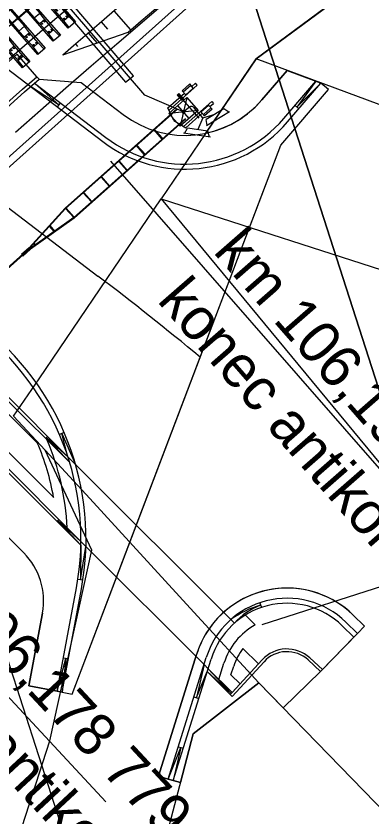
# Model space of a CAD drawing. Extents: x -758836 to -757729, y -1175316 to -1174366.
# Drawn here: x -758398.33 to -758387.81, y -1174860.97 to -1174837.29 of the extents above; entities that cross this region are included whole.
import ezdxf

# ---------------------------------------------------------------- set-up
doc = ezdxf.new("R2010")
doc.units = 0
for name, color, linetype in [('_NOR-návrh silná', 7, 'Continuous'), ('_NOR-návrh tenká', 7, 'Continuous'), ('_NOR-osa', 7, 'Continuous'), ('_NOR-pomocná', 7, 'Continuous'), ('_NOR-popis', 7, 'Continuous'), ('_NOR-pražce', 7, 'Continuous'), ('_NOR-přejezdová konstrukce', 7, 'Continuous'), ('_NOR-sanace', 7, 'Continuous'), ('_NOR-svahy', 7, 'Continuous'), ('G_Obvod stavby', 7, 'Continuous'), ('Hranice parcel', 7, 'Continuous'), ('KOS_kabely SSZT', 7, 'Continuous'), ('KOS_PZZ nové', 7, 'Continuous'), ('Vrstva 1', 7, 'Continuous')]:
    doc.layers.add(name, color=color, linetype=linetype)

# ---------------------------------------------------------------- blocks, each defined once
blk = doc.blocks.new('půdorys-SB8')
at = {"layer": '_NOR-pražce'}
for p, q in [((-1.21, 0.109), (-0.96, 0.095)), ((-0.96, 0.095), (-0.56, 0.099)), ((-0.96, 0.095), (-0.96, -0.095)), ((-0.56, 0.099), (-0.32, 0.109)), ((-0.56, 0.099), (-0.56, -0.1)), ((-0.32, 0.109), (0.32, 0.109)), ((-0.32, 0.109), (-0.32, -0.11)), ((0.56, 0.099), (0.32, 0.109)), ((0.32, -0.11), (0.32, 0.109)), ((0.96, 0.095), (0.56, 0.099)), ((0.56, 0.099), (0.56, -0.1)), ((1.21, 0.109), (0.96, 0.095)), ((0.96, 0.095), (0.96, -0.095)), ((-1.21, -0.11), (-0.96, -0.095)), ((-0.96, -0.095), (-0.56, -0.1)), ((-0.56, -0.1), (-0.32, -0.11)), ((-0.32, -0.11), (0.32, -0.11)), ((0.56, -0.1), (0.32, -0.11)), ((0.96, -0.095), (0.56, -0.1)), ((1.21, -0.11), (0.96, -0.095))]:
    blk.add_line(p, q, dxfattribs=at)
blk.add_lwpolyline([(-1.21, 0.142), (1.21, 0.142), (1.21, -0.142), (-1.21, -0.142)], close=True, dxfattribs=at)
for centre in [(-0.916, 0.048), (-0.604, 0.048), (0.604, 0.048), (0.916, 0.048), (-0.916, -0.048), (-0.604, -0.048), (0.604, -0.048), (0.916, -0.048)]:
    blk.add_circle(centre, 0.015, dxfattribs=at)
blk = doc.blocks.new('Závora 8m')
for p, q in [((0.083, -0.373), (-0.058, -0.373)), ((-0.058, -0.448), (-0.058, -0.373)), ((1.054, -0.448), (-0.058, -0.448)), ((1.032, -0.373), (0.382, -0.373)), ((0.542, -0.323), (0.542, -1.27)), ((1.149, -0.771), (1.032, -0.373)), ((0.413, -1.026), (1.122, -0.517)), ((0.413, -0.517), (1.122, -1.026)), ((0.767, -0.517), (0.767, -1.026)), ((0.851, -0.571), (5.271, -0.571)), ((0.851, -0.591), (5.271, -0.591)), ((1.751, -0.591), (1.751, -0.951)), ((1.771, -0.591), (1.771, -0.951)), ((2.451, -0.591), (2.451, -0.951)), ((2.471, -0.591), (2.471, -0.951)), ((3.151, -0.591), (3.151, -0.951)), ((3.171, -0.591), (3.171, -0.951)), ((3.851, -0.591), (3.851, -0.951)), ((3.871, -0.591), (3.871, -0.951)), ((4.551, -0.591), (4.551, -0.951)), ((4.571, -0.591), (4.571, -0.951)), ((5.251, -0.591), (5.251, -0.951)), ((5.271, -0.571), (6.851, -0.741)), ((5.271, -0.591), (5.271, -0.951)), ((5.271, -0.591), (6.851, -0.761)), ((5.951, -0.665), (5.951, -0.878)), ((5.971, -0.667), (5.971, -0.876)), ((1.149, -0.771), (1.032, -1.17)), ((6.851, -0.781), (5.271, -0.951)), ((5.271, -0.971), (6.851, -0.801)), ((6.651, -0.74), (6.651, -0.803)), ((6.671, -0.742), (6.671, -0.801)), ((6.851, -0.741), (7.151, -0.741)), ((8.851, -0.761), (6.851, -0.761)), ((6.851, -0.761), (6.851, -0.781)), ((6.851, -0.761), (7.151, -0.761)), ((8.851, -0.781), (6.851, -0.781)), ((6.851, -0.781), (7.151, -0.781)), ((6.851, -0.801), (7.151, -0.801)), ((7.151, -0.741), (7.151, -0.761)), ((7.151, -0.801), (7.151, -0.781)), ((8.851, -0.761), (8.851, -0.781)), ((1.054, -1.095), (-0.058, -1.095)), ((-0.058, -1.095), (-0.058, -1.17)), ((0.083, -1.17), (-0.058, -1.17)), ((1.032, -1.17), (0.382, -1.17)), ((0.851, -0.951), (5.271, -0.951)), ((0.851, -0.971), (5.271, -0.971))]:
    blk.add_line(p, q)
for points in [[(0.382, -0.434), (0.083, -0.434), (0.083, -0.274), (0.382, -0.274)], [(0.382, -0.324), (0.083, -0.324), (0.083, -0.274), (0.382, -0.274)], [(0.413, -0.517), (1.122, -0.517), (1.122, -1.026), (0.413, -1.026)], [(0.382, -1.109), (0.083, -1.109), (0.083, -1.269), (0.382, -1.269)], [(0.382, -1.219), (0.083, -1.219), (0.083, -1.269), (0.382, -1.269)]]:
    blk.add_lwpolyline(points, close=True)
blk.add_lwpolyline([(0.507, -1.048), (0.507, -1.27), (0.578, -1.27), (0.578, -1.048)])
for start, end in [(130.1075, 310.1075), (310.1075, 130.1075)]:
    blk.add_arc((0.767, -0.771), 0.0422, start, end)
blk = doc.blocks.new('A$C45C32C5D')
for p, q in [((0.338, 0.725), (0, 0)), ((0.328, 0.702), (0.449, 0.568)), ((0.011, 0.023), (0.192, 0.016))]:
    blk.add_line(p, q)
blk.add_lwpolyline([(0.449, 0.568), (0.192, 0.016)])
blk = doc.blocks.new('A$C45E25FDC')
for p, q in [((0.029, 0.671), (0.224, 0.671)), ((0.341, 0.159), (0.341, 0.557)), ((0.341, 0.159), (0, 0))]:
    blk.add_line(p, q)
blk.add_arc((0.227, 0.557), 0.115, 0.0129, 91.4438)

msp = doc.modelspace()

# ---------------------------------------------------------------- linework, layer by layer
at = {"layer": '_NOR-návrh silná'}
for p, q in [((-758398.635, -1174848.483), (-758396.798, -1174850.321)), ((-758399.199, -1174850.041), (-758396.41, -1174852.83)), ((-758388.58, -1174855.21), (-758388.234, -1174855.546)), ((-758393.827, -1174859.853), (-758392.706, -1174856.261)), ((-758389.269, -1174856.616), (-758389.641, -1174856.272)), ((-758391.944, -1174857.296), (-758391.056, -1174856.33)), ((-758392.651, -1174856.589), (-758391.944, -1174857.296))]:
    msp.add_line(p, q, dxfattribs=at)
for points in [[(-758409.317, -1174830.673), (-758395.764, -1174841.002)], [(-758390.302, -1174840.423), (-758389.316, -1174839.272)], [(-758396.968, -1174857.284), (-758396.396, -1174854.23)]]:
    msp.add_lwpolyline(points, dxfattribs=at)
for centre, radius, start, end in [((-758393.34, -1174837.82), 4, 232.6885, 319.4185), ((-758404.26, -1174852.758), 8, 349.3996, 52.6885), ((-758390.32, -1174857.006), 2.5, 45.9171, 162.6626), ((-758390.32, -1174857.006), 1, 47.2605, 137.4155)]:
    msp.add_arc(centre, radius, start, end, dxfattribs=at)
at = {"layer": '_NOR-návrh tenká'}
for p, q in [((-758410.366, -1174852.055), (-758391.422, -1174835.079)), ((-758410.212, -1174852.218), (-758391.278, -1174835.252)), ((-758389.466, -1174839.216), (-758390.023, -1174839.982)), ((-758397.056, -1174839.923), (-758397.897, -1174839.377)), ((-758397.781, -1174839.276), (-758397.056, -1174839.923)), ((-758390.023, -1174839.982), (-758389.316, -1174839.272)), ((-758397.101, -1174839.983), (-758397.01, -1174839.863)), ((-758389.966, -1174840.031), (-758390.08, -1174839.934)), ((-758398.665, -1174848.567), (-758396.746, -1174850.486)), ((-758398.767, -1174848.847), (-758397.7, -1174849.914)), ((-758396.907, -1174849.607), (-758397.045, -1174849.666)), ((-758396.798, -1174850.321), (-758396.976, -1174849.636)), ((-758396.976, -1174849.636), (-758396.571, -1174850.548)), ((-758399.067, -1174849.678), (-758397.216, -1174851.529)), ((-758397.453, -1174849.779), (-758397.396, -1174849.723)), ((-758396.746, -1174850.486), (-758397.425, -1174849.751)), ((-758397.425, -1174849.751), (-758396.798, -1174850.321)), ((-758399.229, -1174850.124), (-758396.412, -1174852.941)), ((-758396.798, -1174850.321), (-758396.571, -1174850.548)), ((-758396.571, -1174850.548), (-758391.981, -1174855.138)), ((-758397.119, -1174852.234), (-758397.063, -1174852.178)), ((-758396.412, -1174852.941), (-758397.091, -1174852.206)), ((-758397.091, -1174852.206), (-758396.41, -1174852.83)), ((-758396.412, -1174852.941), (-758396.427, -1174853.961)), ((-758396.427, -1174853.961), (-758396.263, -1174852.977)), ((-758396.41, -1174852.83), (-758396.263, -1174852.977)), ((-758392.771, -1174856.469), (-758396.263, -1174852.977)), ((-758396.353, -1174853.972), (-758396.501, -1174853.949)), ((-758391.122, -1174854.639), (-758391.074, -1174854.781)), ((-758391.549, -1174855.004), (-758391.257, -1174855.296)), ((-758391.981, -1174855.138), (-758391.875, -1174855.244)), ((-758388.685, -1174855.318), (-758388.338, -1174855.654)), ((-758389.325, -1174856.673), (-758388.234, -1174855.546)), ((-758391.621, -1174855.992), (-758391.165, -1174856.449)), ((-758397.115, -1174857.256), (-758396.858, -1174856.287)), ((-758396.858, -1174856.287), (-758396.968, -1174857.284)), ((-758396.784, -1174856.301), (-758396.931, -1174856.274)), ((-758393.684, -1174859.898), (-758392.563, -1174856.306)), ((-758392.771, -1174856.469), (-758392.997, -1174857.446)), ((-758392.771, -1174856.469), (-758392.651, -1174856.589)), ((-758392.332, -1174856.908), (-758392.181, -1174856.425)), ((-758391.975, -1174856.771), (-758391.895, -1174856.515)), ((-758391.942, -1174857.412), (-758390.997, -1174856.384)), ((-758389.325, -1174856.673), (-758389.695, -1174856.331)), ((-758392.997, -1174857.446), (-758392.678, -1174856.675)), ((-758392.678, -1174856.675), (-758391.942, -1174857.412)), ((-758392.678, -1174856.675), (-758391.972, -1174857.324)), ((-758391.972, -1174857.324), (-758392.651, -1174856.589)), ((-758391.975, -1174856.771), (-758391.707, -1174857.038)), ((-758393.069, -1174857.424), (-758392.926, -1174857.468)), ((-758391.944, -1174857.296), (-758392.001, -1174857.353)), ((-758393.529, -1174858.899), (-758393.386, -1174858.943)), ((-758393.827, -1174859.853), (-758393.458, -1174858.921)), ((-758393.458, -1174858.921), (-758393.684, -1174859.898)), ((-758393.827, -1174859.853), (-758393.684, -1174859.898))]:
    msp.add_line(p, q, dxfattribs=at)
for points in [[(-758396.95, -1174838.443), (-758396.628, -1174838.163), (-758395.875, -1174837.512), (-758395.12, -1174836.864), (-758394.364, -1174836.218), (-758393.605, -1174835.574), (-758392.844, -1174834.933), (-758392.082, -1174834.295), (-758391.318, -1174833.659), (-758390.551, -1174833.025), (-758389.782, -1174832.394)], [(-758396.95, -1174838.443), (-758395.018, -1174837.764), (-758394.632, -1174837.434), (-758393.877, -1174836.789), (-758393.121, -1174836.147), (-758392.362, -1174835.508), (-758391.601, -1174834.871), (-758390.839, -1174834.236), (-758390.074, -1174833.604), (-758389.306, -1174832.974)], [(-758398.755, -1174838.756), (-758398.003, -1174838.099), (-758397.25, -1174837.445), (-758396.495, -1174836.792)], [(-758391.061, -1174839.772), (-758390.315, -1174838.9), (-758389.466, -1174839.216)], [(-758397.65, -1174839.161), (-758396.408, -1174839.254), (-758395.158, -1174840.206)], [(-758390.416, -1174840.325), (-758389.466, -1174839.216), (-758389.316, -1174839.272)], [(-758397.781, -1174839.276), (-758395.673, -1174840.883)], [(-758396.968, -1174857.284), (-758396.673, -1174857.339), (-758390.499, -1174841.114), (-758389.088, -1174839.467), (-758389.316, -1174839.272)], [(-758401.824, -1174840.47), (-758395.906, -1174844.98)], [(-758398.099, -1174853.163), (-758399.469, -1174851.794)], [(-758396.968, -1174857.284), (-758397.115, -1174857.256), (-758396.544, -1174854.202)], [(-758397.115, -1174857.256), (-758397.951, -1174857.1), (-758397.548, -1174854.945)], [(-758388.234, -1174855.546), (-758388.025, -1174855.331), (-758388.372, -1174854.995)], [(-758392.992, -1174856.172), (-758394.114, -1174859.764), (-758393.827, -1174859.853)], [(-758393.684, -1174859.898), (-758393.467, -1174859.955), (-758393.09, -1174858.52), (-758391.15, -1174857.01), (-758390.43, -1174857.749), (-758389.325, -1174856.673)]]:
    msp.add_lwpolyline(points, dxfattribs=at)
for centre, radius, start, end in [((-758393.34, -1174837.82), 3, 232.6885, 319.4185), ((-758393.34, -1174837.82), 3.85, 232.6885, 319.4185), ((-758456.521, -1174924.515), 100, 50.47712, 52.68848), ((-758404.26, -1174852.758), 7.85, 349.3996, 52.6885), ((-758404.26, -1174852.758), 7.45, 2.5794, 23.2511), ((-758404.26, -1174852.758), 7.15, 9.8988, 23.4389), ((-758399.514, -1174854.577), 2, 349.3996, 45), ((-758390.32, -1174857.006), 2.8, 45.9171, 162.6626), ((-758390.32, -1174857.006), 2.35, 45.9171, 162.6626), ((-758390.317, -1174857.442), 2.842, 105.9509, 125.8252), ((-758390.38, -1174856.584), 2.007, 110.9778, 138.1294), ((-758390.32, -1174857.006), 1.95, 118.725, 162.6626), ((-758390.32, -1174857.006), 1.65, 142.0851, 162.6626), ((-758390.32, -1174857.006), 0.92, 47.2605, 137.4155)]:
    msp.add_arc(centre, radius, start, end, dxfattribs=at)
at = {"layer": '_NOR-osa'}
msp.add_lwpolyline([(-758398.496, -1174837.534), (-758397.741, -1174836.878)], dxfattribs=at)
at = {"layer": '_NOR-pomocná'}
for points in [[(-758417.595, -1174755.224), (-758317.652, -1174723.031), (-758272.123, -1174864.38), (-758372.066, -1174896.572)], [(-758517.538, -1174787.416), (-758417.595, -1174755.224), (-758372.066, -1174896.572), (-758472.009, -1174928.764)]]:
    msp.add_lwpolyline(points, close=True, dxfattribs=at)
at = {"layer": '_NOR-popis'}
for p, q in [((-758395.533, -1174841.585), (-758386.352, -1174852.094)), ((-758362.304, -1174846.032), (-758391.059, -1174855.295)), ((-758403.828, -1174851.775), (-758395.679, -1174860.526))]:
    msp.add_line(p, q, dxfattribs=at)
msp.add_lwpolyline([(-758398.823, -1174886.544), (-758389.781, -1174883.631), (-758402.76, -1174843.338)], dxfattribs=at)
at = {"layer": '_NOR-přejezdová konstrukce'}
msp.add_line((-758397.716, -1174839.086), (-758398.296, -1174838.422), dxfattribs=at)
for points in [[(-758404.537, -1174843.996), (-758403.933, -1174843.446), (-758403.193, -1174842.775), (-758402.452, -1174842.107), (-758401.709, -1174841.44), (-758400.965, -1174840.776), (-758400.219, -1174840.113), (-758399.471, -1174839.452), (-758398.722, -1174838.793), (-758398.296, -1174838.422)], [(-758403.943, -1174844.648), (-758403.34, -1174844.099), (-758402.602, -1174843.43), (-758401.862, -1174842.763), (-758401.121, -1174842.097), (-758400.378, -1174841.434), (-758399.634, -1174840.773), (-758398.888, -1174840.114), (-758398.14, -1174839.457), (-758397.716, -1174839.086)], [(-758403.943, -1174844.648), (-758403.876, -1174844.722), (-758403.272, -1174844.173), (-758402.534, -1174843.504), (-758401.795, -1174842.837), (-758401.054, -1174842.172), (-758400.312, -1174841.509), (-758399.568, -1174840.848), (-758398.822, -1174840.189), (-758398.074, -1174839.532), (-758397.65, -1174839.161), (-758397.716, -1174839.086)]]:
    msp.add_lwpolyline(points, dxfattribs=at)
at = {"layer": '_NOR-sanace'}
msp.add_lwpolyline([(-758398.347, -1174840.728), (-758397.601, -1174840.072), (-758396.854, -1174839.418), (-758396.104, -1174838.767), (-758395.353, -1174838.118), (-758394.6, -1174837.472), (-758393.845, -1174836.827)], dxfattribs=at)
at = {"layer": '_NOR-svahy'}
for points in [[(-758395.436, -1174837.135), (-758394.948, -1174837.704)], [(-758395.816, -1174837.461), (-758395.623, -1174837.685)], [(-758396.194, -1174837.788), (-758395.936, -1174838.087)], [(-758396.573, -1174838.115), (-758396.508, -1174838.19)], [(-758396.95, -1174838.443), (-758396.95, -1174838.443)]]:
    msp.add_lwpolyline(points, dxfattribs=at)
at = {"layer": 'G_Obvod stavby'}
for p, q in [((-758390.315, -1174838.9), (-758391.061, -1174839.772)), ((-758397.548, -1174854.945), (-758397.951, -1174857.1)), ((-758388.234, -1174855.546), (-758388.338, -1174855.654)), ((-758388.338, -1174855.654), (-758389.269, -1174856.616)), ((-758394.114, -1174859.764), (-758392.992, -1174856.172)), ((-758389.325, -1174856.673), (-758390.43, -1174857.749)), ((-758389.269, -1174856.616), (-758389.325, -1174856.673)), ((-758397.951, -1174857.1), (-758397.115, -1174857.256)), ((-758391.15, -1174857.01), (-758393.09, -1174858.52)), ((-758390.43, -1174857.749), (-758391.15, -1174857.01)), ((-758393.09, -1174858.52), (-758393.467, -1174859.955)), ((-758393.827, -1174859.853), (-758394.114, -1174859.764)), ((-758393.684, -1174859.898), (-758393.827, -1174859.853)), ((-758393.467, -1174859.955), (-758393.684, -1174859.898))]:
    msp.add_line(p, q, dxfattribs=at)
for points in [[(-758392.72, -1174840.756), (-758391.23, -1174838.56), (-758368.37, -1174821.64), (-758340.31, -1174807.33), (-758320.27, -1174796.89), (-758301, -1174790.21), (-758267.96, -1174782.93), (-758224.96, -1174775.27), (-758184.87, -1174772.83), (-758142.71, -1174770.26), (-758089.84, -1174768.68), (-758106.02, -1174731.44), (-758149.09, -1174725.67), (-758199.62, -1174726.6), (-758225.76, -1174732.36), (-758252.17, -1174738.18), (-758254.97, -1174739.34), (-758266.58, -1174744.16), (-758279.45, -1174749.49), (-758302.42, -1174759.02), (-758331.68, -1174770.24), (-758367.17, -1174799.81), (-758405.64, -1174832.2)], [(-758397.115, -1174857.256), (-758396.673, -1174857.339), (-758394.966, -1174852.852), (-758392.882, -1174847.378), (-758392.028, -1174845.133), (-758391.423, -1174843.542), (-758390.499, -1174841.114), (-758389.088, -1174839.467), (-758389.316, -1174839.272), (-758390.315, -1174838.9)], [(-758399.469, -1174851.794), (-758398.099, -1174853.163)], [(-758388.372, -1174854.995), (-758388.025, -1174855.331), (-758388.234, -1174855.546)]]:
    msp.add_lwpolyline(points, dxfattribs=at)
for centre, radius, start, end in [((-758393.34, -1174837.82), 3, 283.4057, 319.4185), ((-758393.34, -1174837.82), 3, 281.9101, 283.4057), ((-758399.514, -1174854.577), 2, 349.3996, 45), ((-758390.32, -1174857.006), 2.8, 45.9171, 145.2386), ((-758390.32, -1174857.006), 2.8, 145.2386, 162.6626)]:
    msp.add_arc(centre, radius, start, end, dxfattribs=at)
at = {"layer": 'Hranice parcel'}
for p, q in [((-758391.23, -1174838.56), (-758394.04, -1174842.7)), ((-758384.91, -1174840.91), (-758391.23, -1174838.56)), ((-758397.47, -1174850.13), (-758398.4, -1174849.12))]:
    msp.add_line(p, q, dxfattribs=at)
for points in [[(-758340.31, -1174807.33), (-758368.37, -1174821.64), (-758391.23, -1174838.56)], [(-758398.4, -1174849.12), (-758397.65, -1174848.02), (-758394.04, -1174842.7)], [(-758394.04, -1174842.7), (-758386.64, -1174845.08), (-758382.66, -1174846.36), (-758379.94, -1174849.4), (-758376.01, -1174853.83)], [(-758394.04, -1174842.7), (-758378.39, -1174861.63), (-758372.47, -1174875.16), (-758371.87, -1174876.54), (-758365.08, -1174901.85)], [(-758410.71, -1174900.14), (-758397.33, -1174858.72), (-758396.09, -1174853.08), (-758397.47, -1174850.13)], [(-758391.15, -1174857.01), (-758393.07, -1174854.92), (-758396.15, -1174851.56), (-758397.47, -1174850.13)], [(-758391.15, -1174857.01), (-758393.09, -1174858.52), (-758410.64, -1174925.24)], [(-758365.08, -1174901.85), (-758366.5, -1174900.55), (-758372.65, -1174883.97), (-758377.61, -1174873.09), (-758384.95, -1174863.38), (-758391.15, -1174857.01)]]:
    msp.add_lwpolyline(points, dxfattribs=at)
at = {"layer": 'KOS_kabely SSZT'}
for points in [[(-758393.377, -1174840.127), (-758394.523, -1174839.636), (-758402.059, -1174830.861), (-758402.489, -1174830.243), (-758402.873, -1174830.574), (-758402.896, -1174831.429), (-758411.837, -1174839.758), (-758412.685, -1174838.202), (-758411.837, -1174839.758), (-758414.56, -1174842.041), (-758415.093, -1174841.478), (-758414.56, -1174842.041), (-758421.625, -1174846.632), (-758424.748, -1174843.672)], [(-758401.943, -1174830.766), (-758402.175, -1174830.957), (-758395.093, -1174839.249), (-758394.861, -1174839.058), (-758401.943, -1174830.766)]]:
    msp.add_lwpolyline(points, dxfattribs=at)
at = {"layer": 'KOS_PZZ nové'}
msp.add_line((-758392.805, -1174840.306), (-758392.446, -1174840.191), dxfattribs=at)
at = {"layer": 'Vrstva 1'}
msp.add_lwpolyline([(-758443.817, -1174881.252), (-758441.673, -1174879.1), (-758423.412, -1174860.854), (-758412.446, -1174850.23), (-758405.322, -1174843.614), (-758399.028, -1174837.996), (-758392.64, -1174832.554), (-758380.106, -1174822.693), (-758371.773, -1174816.721), (-758363.37, -1174811.125), (-758354.46, -1174805.649), (-758345.526, -1174800.592), (-758336.614, -1174795.909), (-758327.338, -1174791.462), (-758317.813, -1174787.314), (-758307.666, -1174783.315), (-758298.059, -1174779.921), (-758285.017, -1174775.914), (-758275.047, -1174773.289)], dxfattribs=at)

# ---------------------------------------------------------------- block references
at = {"layer": '_NOR-pražce'}
for p, rotation in [((-758397.468, -1174836.641), -49.17532330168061), ((-758397.919, -1174837.033), -49.01011836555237), ((-758398.372, -1174837.426), -49.01011829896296), ((-758398.823, -1174837.819), -48.848284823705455)]:
    msp.add_blockref('půdorys-SB8', p, dxfattribs=dict(at, rotation=rotation))
at = {"layer": 'KOS_PZZ nové'}
for name, p, rotation in [('Závora 8m', (-758392.291, -1174840.194), -138.39048976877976), ('A$C45E25FDC', (-758392.957, -1174840.651), 41.22607462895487)]:
    msp.add_blockref(name, p, dxfattribs=dict(at, rotation=rotation))
for p, yscale, rotation in [((-758392.701, -1174840.542), -1, 96.41100027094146), ((-758393.376, -1174840.759), -1.0000000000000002, 56.71869221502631)]:
    msp.add_blockref('A$C45C32C5D', p, dxfattribs=dict(at, yscale=yscale, rotation=rotation))

# ---------------------------------------------------------------- texts
at = {"layer": '_NOR-popis'}
for s, rotation, p in [('km 106,191 956', 311.1419, (-758392.525, -1174844.268)), ('konec antikorozní úpravy upevňovadel', 311.1419, (-758394.182, -1174845.716)), ('km 106,178 779', 312.9634, (-758402.099, -1174852.898)), ('začátek antikorozní úpravy upevňovadel', 312.9634, (-758403.709, -1174854.398))]:
    msp.add_text(s, height=1.25, rotation=rotation, dxfattribs=at).set_placement(p)

doc.saveas('drawing.dxf')
